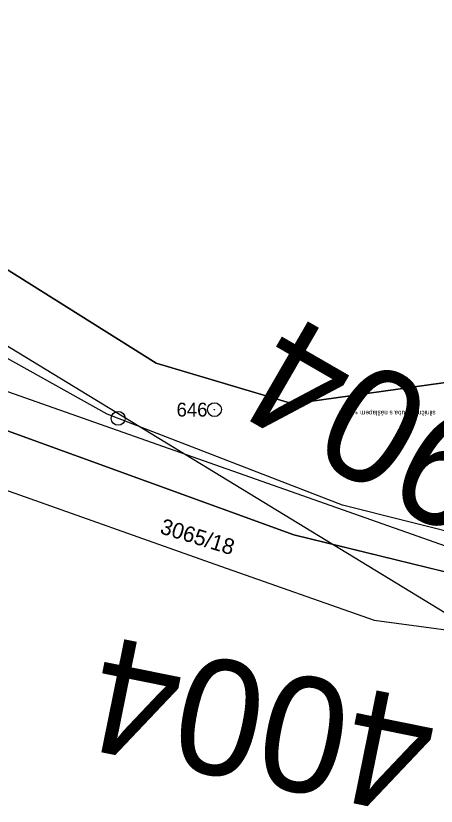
# Model space of a CAD drawing. Extents: x -728802 to -728097, y -1073200 to -1072700.
# Drawn here: x -728571.2 to -728525.7, y -1073068.6 to -1072982.9 of the extents above; entities that cross this region are included whole.
import ezdxf

# ---------------------------------------------------------------- set-up
doc = ezdxf.new("R2010")
doc.units = 0
for name, color, linetype in [('A5_JŽM', 7, 'Continuous'), ('body_ZBP', 7, 'Continuous'), ('body_ZBP-zničený', 7, 'Continuous'), ('body_ZBP_nový', 7, 'Continuous'), ('Hranice parcel', 7, 'Continuous'), ('Projekt', 7, 'Continuous')]:
    doc.layers.add(name, color=color, linetype=linetype)

msp = doc.modelspace()

# ---------------------------------------------------------------- linework, layer by layer
at = {"layer": 'A5_JŽM'}
for points in [[(-728320.8, -1073026.914), (-728374.008, -1073033.722), (-728429.095, -1073040.747), (-728461.932, -1073044.273), (-728481.199, -1073044.815), (-728499.353, -1073043.648), (-728506.01, -1073042.737), (-728514.574, -1073041.329), (-728535.848, -1073035.998), (-728561.353, -1073026.113), (-728583.963, -1073013.524), (-728603.757, -1072998.891), (-728619.185, -1072984.418), (-728634.193, -1072966.825), (-728646.078, -1072949.194), (-728656.182, -1072930.072), (-728664.987, -1072910.227), (-728668.627, -1072901.808), (-728681.252, -1072876.016), (-728691.886, -1072859.663)], [(-728582.13, -1073004.22), (-728556.03, -1073020.59), (-728541.24, -1073024.99), (-728515.38, -1073021.39), (-728515.01, -1073025.35), (-728514.64, -1073029.26), (-728513.66, -1073035.13), (-728513.22, -1073039.89), (-728508.93, -1073042.5), (-728509.9, -1073046.86), (-728541.12, -1073039.22), (-728572.55, -1073027.78)]]:
    msp.add_lwpolyline(points, dxfattribs=at)
msp.add_circle((-728560.163, -1073026.574), 0.75, dxfattribs=at)
at = {"layer": 'body_ZBP'}
msp.add_line((-728524.749, -1073047.651), (-728613.694, -1072993.47), dxfattribs=at)
msp.add_lwpolyline([(-728590.936, -1073017.063), (-728505.859, -1073047.04)], dxfattribs=at)
at = {"layer": 'Hranice parcel'}
msp.add_line((-728541.12, -1073039.22), (-728509.9, -1073046.86), dxfattribs=at)
for points in [[(-728509.9, -1073046.86), (-728508.93, -1073042.5), (-728513.22, -1073039.89), (-728513.66, -1073035.13), (-728514.64, -1073029.26), (-728515.01, -1073025.35), (-728515.38, -1073021.39), (-728541.24, -1073024.99), (-728556.03, -1073020.59), (-728582.13, -1073004.22), (-728604.14, -1072988.92), (-728619.81, -1072972.56), (-728640.48, -1072947.72), (-728648.31, -1072932.44), (-728664.64, -1072897.67), (-728681.24, -1072865.51), (-728697.08, -1072846.24), (-728715.84, -1072827.08), (-728724.75, -1072819.77), (-728735.02, -1072812.66), (-728738.25, -1072810.52), (-728762.66, -1072797.6), (-728789.42, -1072788.62), (-728800, -1072785.753)], [(-728581.66, -1073022.5), (-728572.55, -1073027.78), (-728541.12, -1073039.22)], [(-728581.13, -1073030.83), (-728573.14, -1073034.08), (-728549.07, -1073042.59), (-728532.43, -1073048.47), (-728518.44, -1073050.34), (-728510.92, -1073051.33), (-728509.9, -1073046.86)]]:
    msp.add_lwpolyline(points, dxfattribs=at)
for radius in [0.75, 0.03]:
    msp.add_circle((-728549.73, -1073025.63), radius, dxfattribs=at)

# ---------------------------------------------------------------- texts
at = {"layer": 'body_ZBP-zničený'}
msp.add_text('904', height=12.5, rotation=149.98584, dxfattribs=at).set_placement((-728517.285, -1073028.961))
at = {"layer": 'body_ZBP_nový'}
msp.add_text('4004', height=12.5, rotation=168.54326, dxfattribs=at).set_placement((-728525.117, -1073057.497))
at = {"layer": 'Hranice parcel'}
msp.add_text('646', height=1.5, dxfattribs=at).set_placement((-728553.833, -1073026.379))
msp.add_text('3065/18', height=1.7, rotation=343, dxfattribs=at).set_placement((-728555.728, -1073039.02))
at = {"layer": 'Projekt'}
msp.add_text('silniční obruba s nášlapem +12cm', height=0.5, rotation=180, dxfattribs=at).set_placement((-728525.769, -1073025.756))

doc.saveas('drawing.dxf')
